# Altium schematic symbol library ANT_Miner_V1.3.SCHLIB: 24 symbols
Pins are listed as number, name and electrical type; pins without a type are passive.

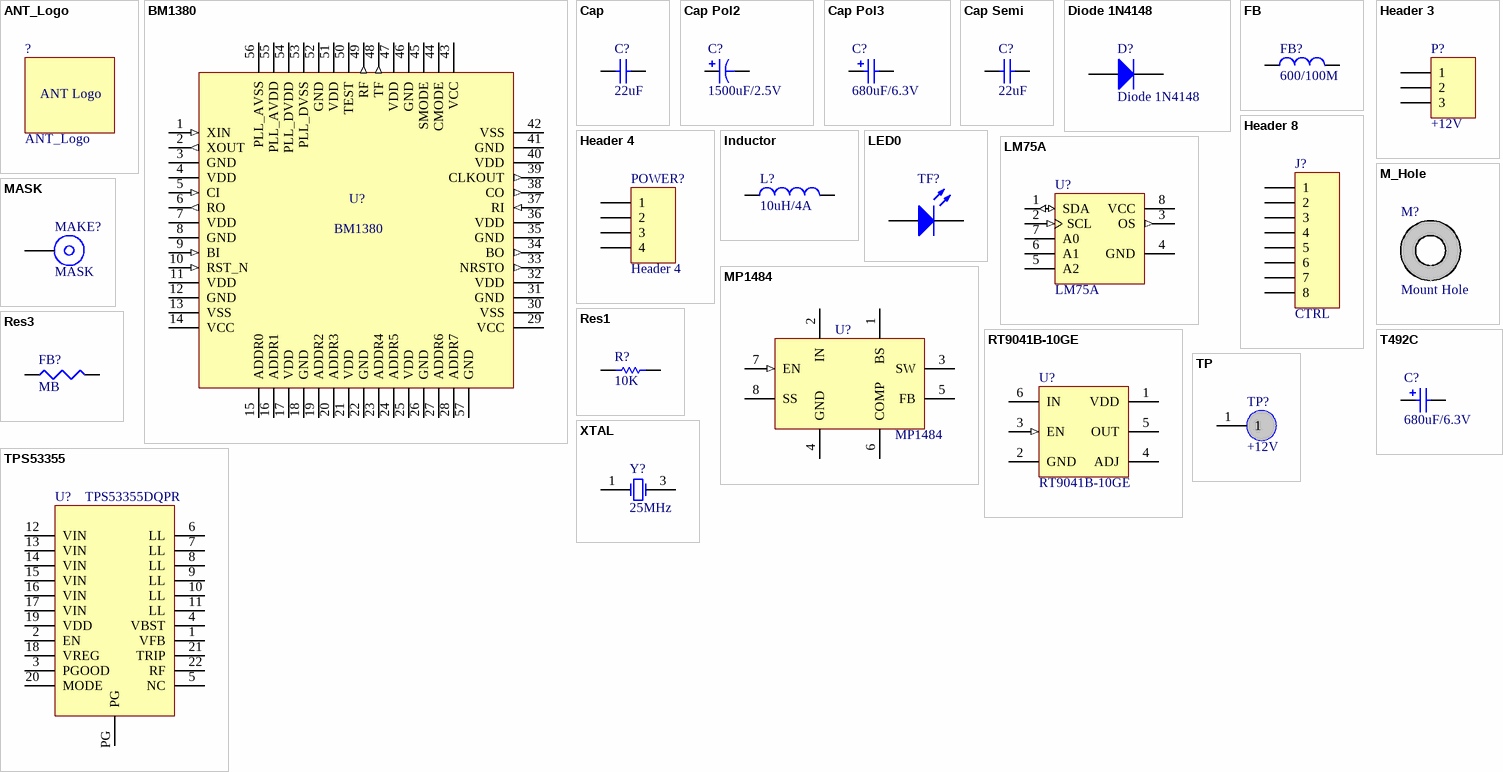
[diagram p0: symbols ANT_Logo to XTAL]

## ANT_Logo
designator ?
footprint ANT_Logo_930x370

## BM1380
designator U?
footprint QFN56
pins: 1 XIN (in), 2 XOUT (out), 3 GND (power), 4 VDD (power), 5 CI (in), 6 RO (out), 7 VDD (power), 8 GND (power), 9 BI (in), 10 RST_N (in), 11 VDD (power), 12 GND (power), 13 VSS (power), 14 VCC (power), 15 ADDR0, 16 ADDR1, 17 VDD (power), 18 GND (power), 19 ADDR2, 20 ADDR3, 21 VDD (power), 22 GND (power), 23 ADDR4, 24 ADDR5, 25 VDD (power), 26 GND (power), 27 ADDR6, 28 ADDR7, 29 VCC (power), 30 VSS (power), 31 GND (power), 32 VDD (power), 33 NRSTO (out), 34 BO (out), 35 GND (power), 36 VDD (power), 37 RI (in), 38 CO (out), 39 CLKOUT (out), 40 VDD (power), 41 GND (power), 42 VSS (power), 43 VCC (power), 44 CMODE, 45 SMODE, 46 GND (power), 47 VDD (power), 48 TF (out), 49 RF (out), 50 TEST, 51 VDD (power), 52 GND (power), 53 PLL_DVSS (power), 54 PLL_DVDD (power), 55 PLL_AVDD (power), 56 PLL_AVSS (power), 57 GND (power)

## Cap
designator C?, comment 22uF
Capacitor
footprint CC0603(1608) (Chip Capacitor, Body 1.6x0.8mm, IPC High Density)
footprint CC0805(2012) (Chip Capacitor, Body 2.0x1.3mm, IPC High Density)
footprint CC1210(3225) (Chip Capacitor, Body 3.2x2.5mm, IPC High Density)
pins: 1, 2

## Cap Pol2
designator C?, comment value 1500uF/2.5V  (hidden comment: 1500uF/4V)
Polarized Capacitor (SMD)
footprint E12 (SVP)
footprint F12 (SVP)
pins: 1, 2

## Cap Pol3
designator C?, comment 680uF/6.3V
Polarized Capacitor (Surface Mount)
footprint D (Capacitor, SM Tantalum; Body 7.3 x 4.3 mm (LxW typ))
footprint 1812 (Chip Capacitor, Body 4.5x3.2mm, IPC High Density)
footprint 1825 (Chip Capacitor, Body 4.5x6.4mm, IPC High Density)
footprint C2225 (Chip Capacitor, Body 5.7x6.4mm, IPC High Density)
footprint 2220 (Chip Capacitor, Body 5.7x5.0mm, IPC High Density)
simulation model CAP (Capacitor)
signal-integrity model Cap Pol
pins: 1, 2
1 alternate drawing of the same symbol

## Cap Semi
designator C?, comment 22uF
Capacitor (Semiconductor SIM Model)
footprint C1206 (Chip Capacitor, Body 3.2x1.6mm, IPC High Density)
footprint 0402 (Chip Capacitor, Body 1.0x0.5mm, IPC High Density)
footprint C2512 (Chip Capacitor, Body 2.54x1.27mm, IPC High Density)
footprint 1608[0603] (Chip Capacitor, Body 1.6x0.8mm, IPC High Density)
footprint CAPC3225N (Chip Capacitor, Body 3.2x2.5mm, IPC Medium Density)
simulation model CAP (Semiconductor Capacitor)
signal-integrity model Cap Semi
footprint CAP1210(3225)_TAN
pins: 1, 2

## Diode 1N4148
designator D?
High Conductance Fast Diode
footprint CD3216-1206 (Chip Diode; Body 3.2 x 1.6 mm (LxW typ))
simulation model 1N4148 (DIODE)
signal-integrity model 1N4148
pins: 1 A, 2 K

## FB
designator FB?, comment 600/100M
Inductor; Code_IEC: 1005
simulation model INDUCTOR (Inductor)
signal-integrity model Inductor
footprint FB0603(1608) (Ferrite Bead)
footprint FB0402(1005) (Ferrite Bead)
pins: 1, 2

## Header 3
designator P?, comment +12V
Header, 3-Pin
footprint HDR1X3 (Connector; Header; 3 Position)
signal-integrity model Connector
footprint TERMINAL_3
pins: 1, 2, 3

## Header 4
designator POWER?
Header, 4-Pin
signal-integrity model Connector
footprint 4Pin_180
pins: 1, 2, 3, 4

## Header 8
designator J?, comment CTRL
Header, 8-Pin
signal-integrity model Connector
footprint 8Pin_180
pins: 1, 2, 3, 4, 5, 6, 7, 8

## Inductor
designator L?, comment 10uH/4A
Inductor; Code_IEC: 1005
footprint 0402-A (Chip Inductor, Body 1.0x0.5mm, IPC High Density)
footprint INDC1608L (Chip Inductor, Body 1.6x0.8mm, IPC High Density)
footprint 2029 (Chip Inductor, Body 2.0x1.2mm, IPC High Density)
footprint 0603 (Chip Inductor, Body 0.6x0.3mm, IPC High Density)
footprint INDC3216 (Chip Inductor, Body 3.2x1.6mm, IPC High Density)
footprint INDC4532 (Chip Inductor, Body 4.5x3.2mm, IPC High Density)
simulation model INDUCTOR (Inductor)
signal-integrity model Inductor
footprint 6-0805_M (Chip Resistor, Body 2.0x1.2mm, IPC Low Density)
footprint 74456047 (WE-PD4 SMD Power Inductor)
footprint SMD_L_12x12
footprint SMD_L_7.0x7.8
footprint SMD_L_7.4x7.4
pins: 1, 2

## LED0
designator TF?, comment Green  (value not drawn)
Typical INFRARED GaAs LED
simulation model LED0 (Diode)
footprint DIODE0805
footprint LED0402(1005) (Chip LED Body 1.0x0.5mm, IPC High Density)
footprint LED0603(1608) (Chip LED, Body 1.6x0.8mm, IPC High Density)
pins: 1 A, 2 K

## LM75A
designator U?
NXP Digital temperature sensor and thermal watchdog
footprint SO8_L (Footprint not found)
pins: 1 SDA (io), 2 SCL (in), 3 OS (out), 4 GND (power), 5 A2, 6 A1, 7 A0, 8 VCC

## M_Hole
designator M?, comment Mount Hole
footprint MHOLE1
footprint MHOLE2
footprint HOLE_3.2
pins: 0 PIN (power)

## MASK
designator MAKE?
footprint MASK (SMD MASK 1mm)
pins: 1

## MP1484
designator U?
footprint SOIC8N_L (Footprint not found)
footprint SOIC8L
pins: 0 hidden to GND, 1 BS, 2 IN (power), 3 SW, 4 GND (power), 5 FB, 6 COMP, 7 EN (in), 8 SS

## Res1
designator R?, comment 10K
Resistor
footprint AXIAL-0.3 (Axial Device, Thru-Hole; 2 Leads; 0.3 in Pin Spacing)
simulation model RESISTOR (Resistor)
signal-integrity model Res
footprint 6-0805_M (Chip Resistor, Body 2.0x1.2mm, IPC Low Density)
footprint LED0603(1608) (Chip LED, Body 1.6x0.8mm, IPC High Density)
footprint RR0603(1608) (Chip Resistor, Body 1.6x0.8mm, IPC High Density)
pins: 1, 2

## Res3
designator FB?, comment MB
Resistor
footprint C1206 (Chip Capacitor, Body 3.2x1.6mm, IPC High Density)
footprint 14-1210 (Chip Resistor, Body 3.2x2.5mm, IPC High Density)
footprint 12Z-2010 (Chip Resistor, Body 5.0x2.5mm, IPC High Density)
footprint RESC6332 (Chip Resistor, Body 6.3x3.2mm, IPC High Density)
simulation model RESISTOR (Resistor)
signal-integrity model Res
footprint INDC3216L (Chip Inductor, Body 3.2x1.6mm, IPC High Density)
pins: 1, 2

## RT9041B-10GE
designator U?
footprint SOT23-6_L (Footprint not found)
pins: 1 VDD (power), 2 GND (power), 3 EN (in), 4 ADJ, 5 OUT (power), 6 IN (power)

## T492C
designator C?, comment 680uF/6.3V
Solid Tantalum Chip Capacitor, T492 Series - CWR11 Style Per Mil-PRF-55365/8
footprint C (Capacitor, SM Tantalum; Body 6.0 x 3.2 mm (LxW typ))
simulation model CAP (Capacitor)
signal-integrity model T492C
footprint C (Capacitor, SM Tantalum; Body 6.0 x 3.2 mm (LxW typ))
footprint D (Capacitor, SM Tantalum; Body 7.3 x 4.3 mm (LxW typ))
pins: 1, 2
1 alternate drawing of the same symbol

## TP
designator TP?, comment +12V
footprint TP
pins: 1

## TPS53355
designator U?, comment TPS53355DQPR
TI DC-DC,Output 30A.
footprint TPS53355
pins: 1 VFB, 2 EN, 3 PGOOD, 4 VBST, 5 NC, 6 LL, 7 LL, 8 LL, 9 LL, 10 LL, 11 LL, 12 VIN, 13 VIN, 14 VIN, 15 VIN, 16 VIN, 17 VIN, 18 VREG, 19 VDD, 20 MODE, 21 TRIP, 22 RF, PG

## XTAL
designator Y?, comment 25MHz
Crystal Oscillator
simulation model XTAL (Spice Subcircuit)
footprint SMX2
pins: 1 OSC1, 3 OSC2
